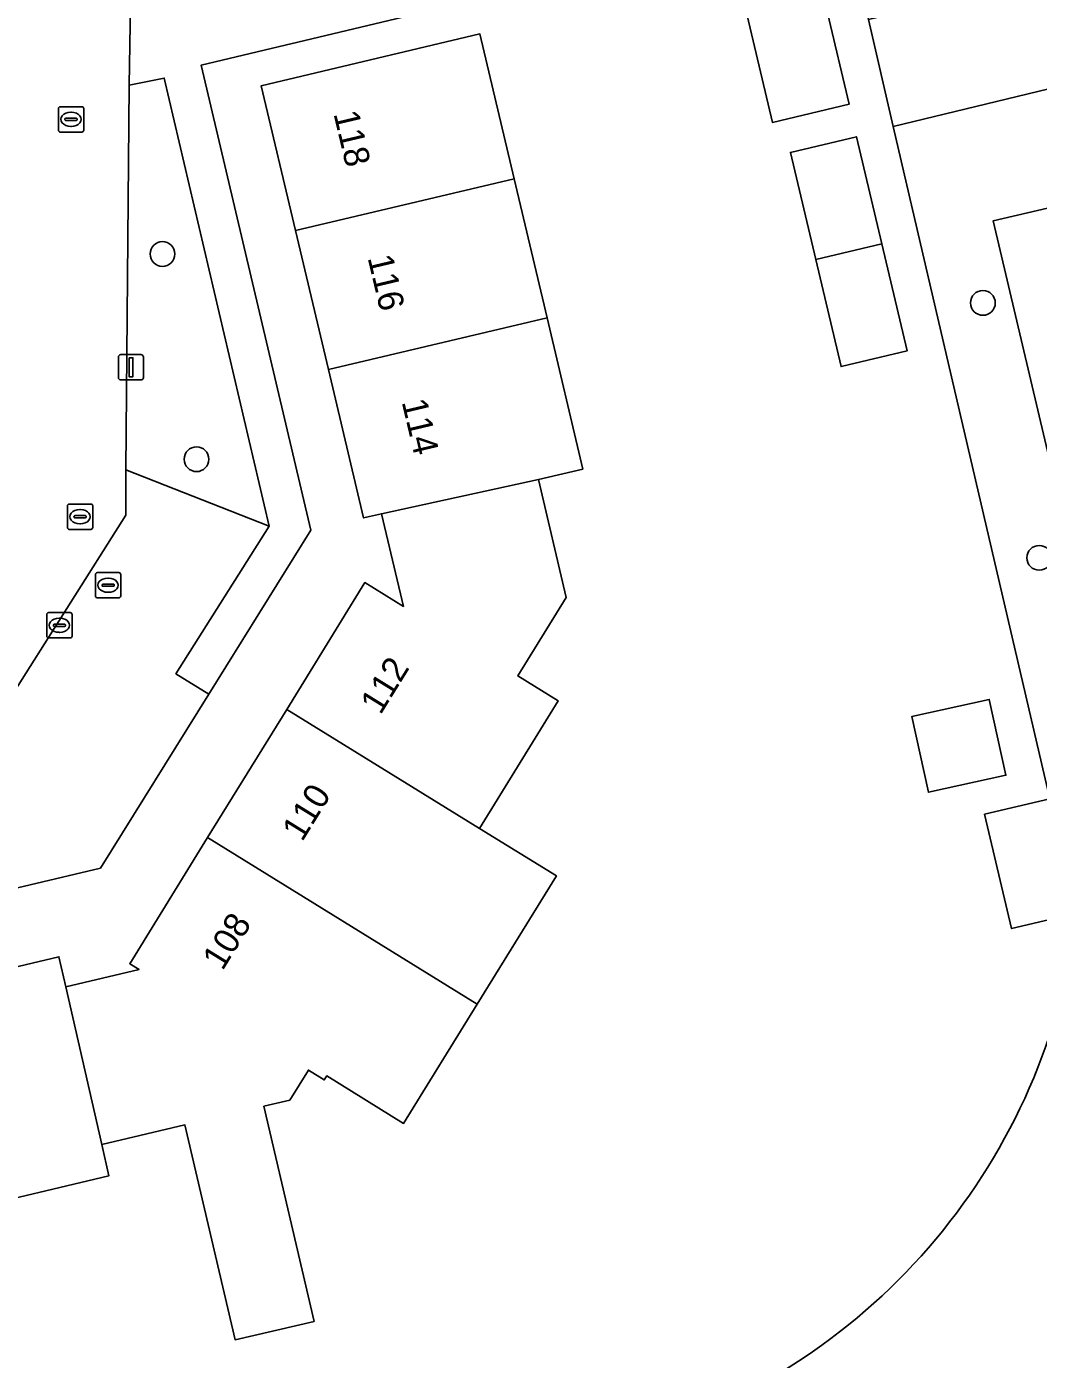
# Model space of a CAD drawing. Extents: x 158031 to 159244, y 380104 to 381214.
# Drawn here: x 158523.3 to 158563.3, y 381003.8 to 381056.5 of the extents above; entities that cross this region are included whole.
import ezdxf

# ---------------------------------------------------------------- set-up
doc = ezdxf.new("R2010")
doc.units = 0
for name, color, linetype in [('IMGEO_Boom', 7, 'Continuous'), ('IMGEO_Erf', 7, 'Continuous'), ('IMGEO_Groenvoorziening', 7, 'Continuous'), ('IMGEO_Kolk', 7, 'Continuous'), ('IMGEO_Lichtmast', 7, 'Continuous'), ('IMGEO_Pand', 7, 'Continuous'), ('IMGEO_Pand_nummerreeks', 7, 'Continuous'), ('IMGEO_Parkeervlak_open', 7, 'Continuous'), ('IMGEO_Rioolput', 7, 'Continuous'), ('IMGEO_Voetpad_open', 7, 'Continuous')]:
    doc.layers.add(name, color=color, linetype=linetype)

msp = doc.modelspace()

# ---------------------------------------------------------------- linework, layer by layer
at = {"layer": 'IMGEO_Boom'}
for centre in [(158528.659, 381047.507), (158561.068, 381045.574), (158530.003, 381039.4), (158563.292, 381035.506)]:
    msp.add_circle(centre, 0.489, dxfattribs=at)
at = {"layer": 'IMGEO_Erf'}
for points in [[(158557.53, 381052.543), (158556.544, 381056.774), (158555.559, 381061.005), (158554.079, 381060.657), (158555.79, 381053.425), (158552.751, 381052.706), (158551.04, 381059.938), (158530.193, 381054.964), (158534.525, 381036.6), (158530.488, 381030.118), (158526.207, 381023.243), (158506.747, 381018.645)], [(158518.732, 381018.368), (158524.566, 381019.748), (158524.846, 381018.564), (158527.733, 381019.247), (158527.365, 381019.474), (158530.442, 381024.458), (158533.567, 381029.52), (158536.657, 381034.525), (158538.174, 381033.588), (158537.309, 381037.247), (158536.6, 381037.079), (158535.214, 381042.94), (158533.915, 381048.431), (158532.561, 381054.153), (158541.198, 381056.196), (158542.553, 381050.47), (158543.851, 381044.979), (158545.263, 381039.012), (158543.507, 381038.597), (158544.608, 381033.942), (158542.693, 381030.84), (158544.291, 381029.853), (158541.183, 381024.818), (158544.218, 381022.944), (158541.093, 381017.882), (158538.183, 381013.168), (158535.147, 381015.042), (158535.052, 381014.888), (158534.422, 381015.277), (158533.689, 381014.089), (158532.666, 381013.847), (158534.647, 381005.349), (158531.525, 381004.621), (158529.547, 381013.109), (158526.263, 381012.332), (158526.537, 381011.096), (158520.773, 381009.733)], [(158564.784, 381021.473), (158562.203, 381020.862), (158561.134, 381025.379), (158563.715, 381025.989), (158557.53, 381052.543)]]:
    msp.add_lwpolyline(points, dxfattribs=at)
for points in [[(158553.466, 381051.52), (158556.073, 381052.137), (158557.074, 381047.905), (158558.075, 381043.675), (158555.468, 381043.058), (158554.467, 381047.29)], [(158561.322, 381029.914), (158561.978, 381026.919), (158558.919, 381026.249), (158558.262, 381029.243)]]:
    msp.add_lwpolyline(points, close=True, dxfattribs=at)
msp.add_arc((158540.283, 381024.438), 24.68, 287.0029, 353.1004, dxfattribs=at)
at = {"layer": 'IMGEO_Groenvoorziening'}
for points in [[(158564.871, 381054.321), (158585.487, 381059.313), (158590.114, 381060.4), (158590.223, 381060.591), (158589.783, 381062.687), (158591.799, 381063.226), (158591.329, 381065.154), (158556.544, 381056.774), (158557.53, 381052.543)], [(158528.727, 381054.456), (158527.348, 381054.168), (158527.206, 381038.984), (158532.876, 381036.753)]]:
    msp.add_lwpolyline(points, close=True, dxfattribs=at)
for points in [[(158564.871, 381054.321), (158557.53, 381052.543), (158563.715, 381025.989)], [(158570.246, 381011.648), (158561.469, 381048.81), (158564.971, 381049.628)]]:
    msp.add_lwpolyline(points, dxfattribs=at)
msp.add_arc((158540.283, 381024.438), 24.68, 287.0029, 353.1004, dxfattribs=at)
at = {"layer": 'IMGEO_Kolk'}
for p, q in [((158524.548, 381052.398), (158524.548, 381053.25)), ((158524.623, 381053.324), (158525.475, 381053.324)), ((158525.549, 381053.25), (158525.549, 381052.398)), ((158524.807, 381052.818), (158524.807, 381052.83)), ((158525.245, 381052.781), (158524.847, 381052.781)), ((158524.85, 381052.867), (158525.248, 381052.867)), ((158525.036, 381053.104), (158525.061, 381053.104)), ((158525.291, 381052.83), (158525.291, 381052.818)), ((158525.475, 381052.324), (158524.623, 381052.324)), ((158525.059, 381052.544), (158525.034, 381052.544))]:
    msp.add_line(p, q, dxfattribs=at)
for points in [[(158524.548, 381052.398), (158524.548, 381053.25)], [(158524.623, 381053.324), (158525.475, 381053.324)], [(158525.549, 381053.25), (158525.549, 381052.398)], [(158525.475, 381052.324), (158524.623, 381052.324)]]:
    msp.add_lwpolyline(points, dxfattribs=at)
for centre, radius, start, end in [((158524.625, 381053.248), 0.0765, 91.552, 178.448), ((158524.625, 381053.248), 0.0765, 91.552, 178.448), ((158525.473, 381053.248), 0.0765, 1.552, 88.448), ((158525.473, 381053.248), 0.0765, 1.552, 88.448), ((158524.847, 381052.827), 0.0403, 85.8775, 175.7526), ((158524.844, 381052.817), 0.0366, 178.938, 274.7102), ((158525.248, 381052.824), 0.043, 264.8664, 352.4533), ((158525.252, 381052.829), 0.0386, 1.7309, 96.639), ((158524.625, 381052.4), 0.0765, 181.552, 268.448), ((158524.625, 381052.4), 0.0765, 181.552, 268.448), ((158525.473, 381052.4), 0.0765, 271.552, 358.448), ((158525.473, 381052.4), 0.0765, 271.552, 358.448)]:
    msp.add_arc(centre, radius, start, end, dxfattribs=at)
for centre, major_axis, ratio, start_param, end_param in [((158525.035, 381052.824), (-0.387, 0.002), 0.722429, 4.712389, 7.853982), ((158525.06, 381052.824), (-0.39, 0.002), 0.717154, 1.570796, 4.712389)]:
    msp.add_ellipse(centre, major_axis=major_axis, ratio=ratio, start_param=start_param, end_param=end_param, dxfattribs=at)
at = {"layer": 'IMGEO_Lichtmast'}
for p, q in [((158526.919, 381042.63), (158526.919, 381043.43)), ((158526.919, 381043.43), (158526.919, 381042.63)), ((158527.019, 381043.53), (158527.809, 381043.53)), ((158527.809, 381043.53), (158527.019, 381043.53)), ((158527.909, 381043.43), (158527.909, 381042.63)), ((158527.909, 381042.63), (158527.909, 381043.43)), ((158527.809, 381042.53), (158527.019, 381042.53)), ((158527.019, 381042.53), (158527.809, 381042.53))]:
    msp.add_line(p, q, dxfattribs=at)
msp.add_lwpolyline([(158527.339, 381043.405), (158527.489, 381043.405), (158527.489, 381042.655), (158527.339, 381042.655), (158527.339, 381043.405)], dxfattribs=at)
for centre, start, end in [((158527.019, 381043.43), 90, 180), ((158527.019, 381043.43), 90, 180), ((158527.809, 381043.43), 0, 90), ((158527.809, 381043.43), 360, 90), ((158527.019, 381042.63), 180, 270), ((158527.019, 381042.63), 180, 270), ((158527.809, 381042.63), 270, 0), ((158527.809, 381042.63), 270, 0)]:
    msp.add_arc(centre, 0.1, start, end, dxfattribs=at)
at = {"layer": 'IMGEO_Pand'}
for points in [[(158551.04, 381059.938), (158552.751, 381052.706), (158555.79, 381053.425), (158554.079, 381060.657)], [(158533.915, 381048.431), (158542.553, 381050.47), (158541.198, 381056.196), (158532.561, 381054.153)], [(158554.467, 381047.29), (158557.074, 381047.905), (158556.073, 381052.137), (158553.466, 381051.52)], [(158535.214, 381042.94), (158543.851, 381044.979), (158542.553, 381050.47), (158533.915, 381048.431)], [(158554.467, 381047.29), (158555.468, 381043.058), (158558.075, 381043.675), (158557.074, 381047.905)], [(158543.507, 381038.597), (158545.263, 381039.012), (158543.851, 381044.979), (158535.214, 381042.94), (158536.6, 381037.079), (158537.309, 381037.247)], [(158533.567, 381029.52), (158541.183, 381024.818), (158544.291, 381029.853), (158542.693, 381030.84), (158544.608, 381033.942), (158543.507, 381038.597), (158537.309, 381037.247), (158538.174, 381033.588), (158536.657, 381034.525)], [(158541.093, 381017.882), (158544.218, 381022.944), (158541.183, 381024.818), (158533.567, 381029.52), (158530.442, 381024.458)], [(158558.262, 381029.243), (158558.919, 381026.249), (158561.978, 381026.919), (158561.322, 381029.914)], [(158564.784, 381021.473), (158563.715, 381025.989), (158561.134, 381025.379), (158562.203, 381020.862)], [(158541.093, 381017.882), (158530.442, 381024.458), (158527.365, 381019.474), (158527.733, 381019.247), (158524.846, 381018.564), (158526.263, 381012.332), (158529.547, 381013.109), (158531.525, 381004.621), (158534.647, 381005.349), (158532.666, 381013.847), (158533.689, 381014.089), (158534.422, 381015.277), (158535.052, 381014.888), (158535.147, 381015.042), (158538.183, 381013.168)], [(158520.773, 381009.733), (158526.537, 381011.096), (158526.263, 381012.332), (158524.846, 381018.564), (158524.566, 381019.748), (158518.732, 381018.368)]]:
    msp.add_lwpolyline(points, close=True, dxfattribs=at)
at = {"layer": 'IMGEO_Parkeervlak_open'}
for points in [[(158566.064, 381049.93), (158565.594, 381050.137), (158565.548, 381050.058), (158565.495, 381049.983), (158565.435, 381049.913), (158565.369, 381049.849), (158565.298, 381049.791), (158565.222, 381049.739), (158565.142, 381049.695), (158565.058, 381049.657), (158564.971, 381049.628), (158561.469, 381048.81), (158570.246, 381011.648), (158573.87, 381012.524), (158573.945, 381012.515), (158574.077, 381012.49), (158574.207, 381012.453), (158574.333, 381012.404), (158574.454, 381012.345), (158574.57, 381012.274), (158574.795, 381012.849)], [(158530.488, 381030.118), (158529.19, 381030.926), (158532.876, 381036.753), (158527.206, 381038.984), (158527.206, 381037.191), (158522.544, 381029.82), (158503.075, 381025.332), (158503.422, 381023.912), (158504.71, 381018.633), (158504.815, 381018.188), (158506.747, 381018.645), (158526.207, 381023.243)]]:
    msp.add_lwpolyline(points, close=True, dxfattribs=at)
at = {"layer": 'IMGEO_Rioolput'}
for p, q in [((158524.904, 381036.704), (158524.904, 381037.556)), ((158524.979, 381037.63), (158525.831, 381037.63)), ((158525.392, 381037.41), (158525.417, 381037.41)), ((158525.905, 381037.556), (158525.905, 381036.704)), ((158525.163, 381037.124), (158525.163, 381037.136)), ((158525.601, 381037.087), (158525.203, 381037.087)), ((158525.206, 381037.173), (158525.604, 381037.173)), ((158525.647, 381037.136), (158525.647, 381037.124)), ((158525.831, 381036.63), (158524.979, 381036.63)), ((158525.415, 381036.85), (158525.39, 381036.85)), ((158526.011, 381033.999), (158526.011, 381034.851)), ((158526.086, 381034.925), (158526.938, 381034.925)), ((158527.012, 381034.851), (158527.012, 381033.999)), ((158526.27, 381034.419), (158526.27, 381034.431)), ((158526.708, 381034.382), (158526.31, 381034.382)), ((158526.313, 381034.468), (158526.711, 381034.468)), ((158526.499, 381034.705), (158526.524, 381034.705)), ((158526.754, 381034.431), (158526.754, 381034.419)), ((158526.938, 381033.925), (158526.086, 381033.925)), ((158526.522, 381034.145), (158526.497, 381034.145)), ((158524.088, 381032.417), (158524.088, 381033.269)), ((158524.163, 381033.343), (158525.015, 381033.343)), ((158525.089, 381033.269), (158525.089, 381032.417)), ((158524.347, 381032.837), (158524.347, 381032.849)), ((158524.785, 381032.8), (158524.387, 381032.8)), ((158524.39, 381032.886), (158524.788, 381032.886)), ((158524.576, 381033.123), (158524.601, 381033.123)), ((158524.831, 381032.849), (158524.831, 381032.837)), ((158525.015, 381032.343), (158524.163, 381032.343)), ((158524.599, 381032.563), (158524.574, 381032.563))]:
    msp.add_line(p, q, dxfattribs=at)
for points in [[(158524.904, 381036.704), (158524.904, 381037.556)], [(158524.979, 381037.63), (158525.831, 381037.63)], [(158525.905, 381037.556), (158525.905, 381036.704)], [(158525.831, 381036.63), (158524.979, 381036.63)], [(158526.011, 381033.999), (158526.011, 381034.851)], [(158526.086, 381034.925), (158526.938, 381034.925)], [(158527.012, 381034.851), (158527.012, 381033.999)], [(158526.938, 381033.925), (158526.086, 381033.925)], [(158524.088, 381032.417), (158524.088, 381033.269)], [(158524.163, 381033.343), (158525.015, 381033.343)], [(158525.089, 381033.269), (158525.089, 381032.417)], [(158525.015, 381032.343), (158524.163, 381032.343)]]:
    msp.add_lwpolyline(points, dxfattribs=at)
for centre, radius, start, end in [((158524.981, 381037.554), 0.0765, 91.552, 178.448), ((158524.981, 381037.554), 0.0765, 91.552, 178.448), ((158525.829, 381037.554), 0.0765, 1.552, 88.448), ((158525.829, 381037.554), 0.0765, 1.552, 88.448), ((158525.203, 381037.133), 0.0403, 85.8775, 175.7526), ((158525.2, 381037.123), 0.0366, 178.938, 274.7102), ((158525.604, 381037.13), 0.043, 264.8664, 352.4533), ((158525.608, 381037.135), 0.0386, 1.7309, 96.639), ((158524.981, 381036.706), 0.0765, 181.552, 268.448), ((158524.981, 381036.706), 0.0765, 181.552, 268.448), ((158525.829, 381036.706), 0.0765, 271.552, 358.448), ((158525.829, 381036.706), 0.0765, 271.552, 358.448), ((158526.088, 381034.849), 0.0765, 91.552, 178.448), ((158526.088, 381034.849), 0.0765, 91.552, 178.448), ((158526.936, 381034.849), 0.0765, 1.552, 88.448), ((158526.936, 381034.849), 0.0765, 1.552, 88.448), ((158526.31, 381034.428), 0.0403, 85.8775, 175.7526), ((158526.307, 381034.418), 0.0366, 178.938, 274.7102), ((158526.711, 381034.425), 0.043, 264.8664, 352.4533), ((158526.715, 381034.43), 0.0386, 1.7309, 96.639), ((158526.088, 381034.001), 0.0765, 181.552, 268.448), ((158526.088, 381034.001), 0.0765, 181.552, 268.448), ((158526.936, 381034.001), 0.0765, 271.552, 358.448), ((158526.936, 381034.001), 0.0765, 271.552, 358.448), ((158524.165, 381033.267), 0.0765, 91.552, 178.448), ((158524.165, 381033.267), 0.0765, 91.552, 178.448), ((158525.013, 381033.267), 0.0765, 1.552, 88.448), ((158525.013, 381033.267), 0.0765, 1.552, 88.448), ((158524.387, 381032.846), 0.0403, 85.8775, 175.7526), ((158524.384, 381032.836), 0.0366, 178.938, 274.7102), ((158524.788, 381032.843), 0.043, 264.8664, 352.4533), ((158524.792, 381032.848), 0.0386, 1.7309, 96.639), ((158524.165, 381032.419), 0.0765, 181.552, 268.448), ((158524.165, 381032.419), 0.0765, 181.552, 268.448), ((158525.013, 381032.419), 0.0765, 271.552, 358.448), ((158525.013, 381032.419), 0.0765, 271.552, 358.448)]:
    msp.add_arc(centre, radius, start, end, dxfattribs=at)
for centre, major_axis, ratio, start_param, end_param in [((158525.391, 381037.13), (-0.387, 0.002), 0.722429, 4.712389, 7.853982), ((158525.416, 381037.13), (-0.39, 0.002), 0.717154, 1.570796, 4.712389), ((158526.498, 381034.425), (-0.387, 0.002), 0.722429, 4.712389, 7.853982), ((158526.523, 381034.425), (-0.39, 0.002), 0.717154, 1.570796, 4.712389), ((158524.575, 381032.843), (-0.387, 0.002), 0.722429, 4.712389, 7.853982), ((158524.6, 381032.843), (-0.39, 0.002), 0.717154, 1.570796, 4.712389)]:
    msp.add_ellipse(centre, major_axis=major_axis, ratio=ratio, start_param=start_param, end_param=end_param, dxfattribs=at)
at = {"layer": 'IMGEO_Voetpad_open'}
msp.add_lwpolyline([(158551.04, 381059.938), (158554.079, 381060.657), (158553.326, 381063.706), (158550.535, 381063.021), (158550.589, 381062.801), (158527.394, 381057.361), (158527.348, 381054.168), (158528.727, 381054.456), (158532.876, 381036.753), (158529.19, 381030.926), (158530.488, 381030.118), (158534.525, 381036.6), (158530.193, 381054.964)], close=True, dxfattribs=at)
msp.add_lwpolyline([(158522.544, 381029.82), (158527.206, 381037.191), (158527.206, 381038.984), (158527.348, 381054.168), (158527.394, 381057.361)], dxfattribs=at)

# ---------------------------------------------------------------- texts
at = {"layer": 'IMGEO_Pand_nummerreeks'}
for s, rotation, p in [('118', 283.3091, (158535.411, 381053.049)), ('116', 283.3091, (158536.758, 381047.36)), ('114', 283.3091, (158538.104, 381041.668)), ('112', 58.3102, (158537.269, 381029.273)), ('110', 58.3102, (158534.175, 381024.261)), ('108', 58.3099, (158531.03, 381019.168))]:
    msp.add_text(s, height=1, rotation=rotation, dxfattribs=at).set_placement(p)

doc.saveas('drawing.dxf')
